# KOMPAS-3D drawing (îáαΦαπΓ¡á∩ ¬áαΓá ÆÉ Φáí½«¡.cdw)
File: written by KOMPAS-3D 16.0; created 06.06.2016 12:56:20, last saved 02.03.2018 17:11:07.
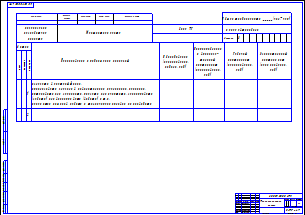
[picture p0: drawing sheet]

Sheet 1: A1, landscape

Title block, sheet 1: name: Технологическая / карта; designation: ДП 009.00.00 4ТЧ; scale: 1:1; sheets: 1; organisation: САТК - 47; sheet format: A1; revision letter: Д; stored path: C:\Documents and Settings\Admin\Мои документы\Мои рисунки\Базылев опер ката.cdw; drawn by: Ковалёв Р.С.; checked by: Ершов М.В.; standards control: Бервинова Н.К.; approved by: Ященко М.К.

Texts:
  Базылев опер карта
  satk
  Normal
  heading 1
  Стили документа
Dimensions and other numbers on the sheet: 1:1; 1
